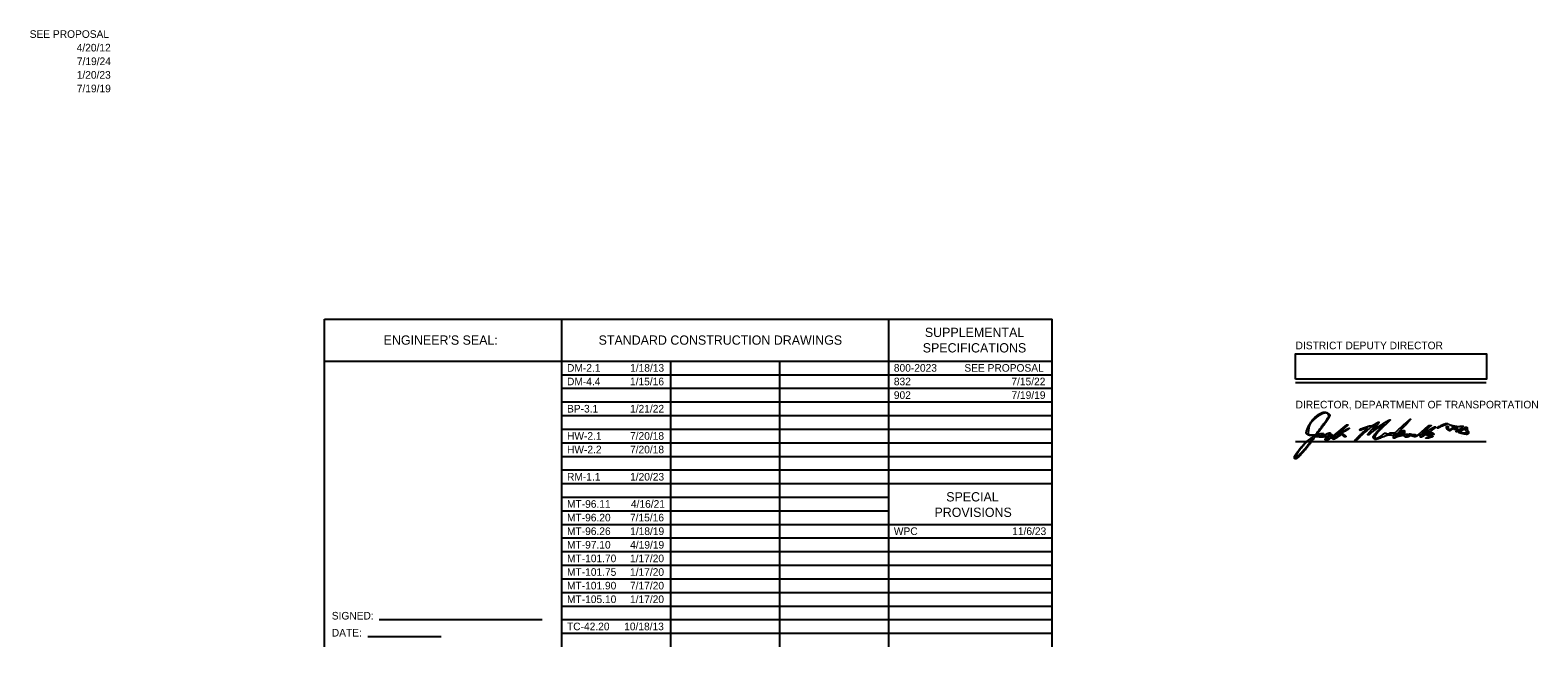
# Model space of a CAD drawing. Extents: x -84548 to 2262448, y -162180 to 525962.
# Drawn here: x 192054 to 338190, y -29401 to 30418 of the extents above; entities that cross this region are included whole.
import ezdxf

# ---------------------------------------------------------------- set-up
doc = ezdxf.new("R2010")
doc.units = 0
for name, color, linetype in [('Default', 7, 'Continuous'), ('GM_X_County', 7, 'Continuous'), ('GM_X_Section', 7, 'Continuous')]:
    doc.layers.add(name, color=color, linetype=linetype)

msp = doc.modelspace()

# ---------------------------------------------------------------- linework, layer by layer
at = {"layer": 'GM_X_County'}
for p, q in [((220590, 2389), (291110, 2389)), ((220590, -29401), (220590, 2389)), ((243590, -29401), (243590, 2389)), ((275270, -29401), (275270, 2389)), ((291110, -29401), (291110, 2389)), ((220590, -1681), (243590, -1681)), ((243590, -1681), (291110, -1681)), ((254150, -29401), (254150, -1681)), ((264710, -29401), (264710, -1681)), ((243590, -3001), (291110, -3001)), ((243590, -4321), (291110, -4321)), ((314711, -3758), (333191, -3758)), ((243590, -5641), (291110, -5641)), ((243590, -6961), (291110, -6961)), ((243590, -8281), (291110, -8281)), ((243590, -9601), (291110, -9601)), ((314711, -9492), (333191, -9492)), ((243590, -10921), (291110, -10921)), ((243590, -12241), (291110, -12241)), ((243590, -13561), (275270, -13561)), ((275270, -13561), (291110, -13561)), ((243590, -14881), (275270, -14881)), ((243590, -16201), (275270, -16201)), ((243590, -17521), (275270, -17521)), ((275270, -17521), (291110, -17521)), ((243590, -18841), (291110, -18841)), ((243590, -20161), (291110, -20161)), ((243590, -21481), (291110, -21481)), ((243590, -22801), (291110, -22801)), ((243590, -24121), (291110, -24121)), ((243590, -25441), (291110, -25441)), ((225889, -26751), (241697, -26751)), ((243590, -26761), (291110, -26761)), ((224793, -28401), (231893, -28401)), ((243590, -28081), (291110, -28081))]:
    msp.add_line(p, q, dxfattribs=at)
msp.add_lwpolyline([(314711, -3441), (314711, -987), (333213, -987), (333213, -3441)], close=True, dxfattribs=at)
at = {"layer": 'GM_X_Section'}
for p, q in [((317152, -8409), (317152, -8409)), ((328448, -8414), (328448, -8414)), ((318845, -9104), (318845, -9104)), ((319081, -8884), (319081, -8884)), ((321044, -9037), (321044, -9037)), ((325148, -8873), (325148, -8873)), ((330837, -8975), (330837, -8975))]:
    msp.add_line(p, q, dxfattribs=at)
for points in [[(324874, -8713), (324719, -8848), (324933, -8745)], [(329840, -8200), (330033, -8087), (329818, -7966)], [(331154, -8641), (331451, -8641), (331299, -8524)], [(316373, -9027), (316535, -8915), (316335, -8911)], [(317655, -9132), (317767, -8961), (317547, -9014)]]:
    msp.add_lwpolyline(points, dxfattribs=at)
for points in [[(316584, -7292), (316232, -7594), (316027, -7932), (315968, -8308)], [(316036, -7877), (316492, -7083), (317591, -6471), (317937, -6818)], [(317890, -6866), (317753, -6644), (317087, -6861), (316584, -7292)], [(317152, -8145), (317793, -7282), (317964, -6986), (317890, -6866)], [(317940, -7146), (317882, -7268), (317609, -7666), (317333, -8033)], [(317937, -6818), (318037, -6917), (318037, -6943), (317940, -7146)], [(316335, -8911), (315818, -8902), (315694, -8474), (316036, -7877)], [(315968, -8308), (315908, -8696), (316021, -8842), (316381, -8842)], [(316381, -8842), (316627, -8842), (316651, -8820), (317152, -8145)], [(317333, -8033), (317057, -8399), (316832, -8719), (316832, -8744)], [(316832, -8744), (316832, -8770), (316913, -8771), (317013, -8748)], [(316887, -8912), (317044, -8975), (317341, -8846), (317249, -8754)], [(317013, -8748), (317148, -8717), (317169, -8723), (317096, -8773)], [(317249, -8754), (317225, -8730), (317258, -8710), (317323, -8710)], [(317323, -8710), (317400, -8710), (317427, -8744), (317402, -8809)], [(317592, -8819), (317745, -8714), (318086, -8622), (318086, -8685)], [(317772, -9238), (317894, -9238), (318560, -8769), (319152, -8265)], [(318086, -8685), (318086, -8709), (318034, -8766), (317971, -8812)], [(319241, -8340), (318748, -8726), (318635, -8840), (318867, -8716)], [(318867, -8716), (318934, -8680), (319060, -8669), (319147, -8691)], [(319100, -8644), (319074, -8644), (319066, -8633), (319081, -8620)], [(319081, -8620), (319189, -8526), (319886, -8178), (319913, -8205)], [(319913, -8205), (319946, -8238), (319193, -8644), (319100, -8644)], [(319147, -8691), (319338, -8739), (319646, -9040), (319505, -9040)], [(319152, -8265), (319419, -8039), (319659, -7854), (319686, -7853)], [(319686, -7853), (319817, -7850), (319694, -7985), (319241, -8340)], [(320925, -8330), (320926, -8275), (321915, -7941), (321998, -7968)], [(322493, -7815), (322442, -7765), (321335, -8646), (320924, -9065)], [(321353, -8248), (321022, -8390), (320923, -8409), (320925, -8330)], [(321044, -8773), (321419, -8412), (321711, -8116), (321693, -8116)], [(321693, -8116), (321675, -8116), (321522, -8175), (321353, -8248)], [(321735, -8842), (321680, -8842), (321833, -8624), (322082, -8345)], [(321910, -8747), (321867, -8799), (321788, -8842), (321735, -8842)], [(323234, -7818), (322975, -7965), (321980, -8663), (321910, -8747)], [(321998, -7968), (322028, -7978), (322184, -7909), (322345, -7814)], [(322082, -8345), (322327, -8072), (322512, -7834), (322493, -7815)], [(322324, -9215), (322191, -9082), (322344, -8817), (322889, -8235)], [(322513, -7996), (322365, -8164), (322244, -8320), (322244, -8344)], [(322244, -8344), (322244, -8367), (322429, -8256), (322656, -8097)], [(322345, -7814), (322761, -7570), (322825, -7640), (322513, -7996)], [(323373, -7890), (322847, -8385), (322376, -8956), (322376, -9098)], [(322471, -9172), (322586, -9172), (323015, -8933), (323207, -8763)], [(322656, -8097), (323081, -7798), (323775, -7390), (323858, -7390)], [(322889, -8235), (323133, -7975), (323288, -7787), (323234, -7818)], [(323207, -8763), (323314, -8668), (323382, -8654), (323508, -8701)], [(323858, -7390), (323883, -7390), (323665, -7615), (323373, -7890)], [(323508, -8701), (323614, -8742), (323713, -8738), (323798, -8690)], [(323798, -8690), (323869, -8651), (324018, -8626), (324131, -8635)], [(324131, -8635), (324307, -8650), (324431, -8563), (325055, -7989)], [(324422, -8758), (324422, -8720), (324368, -8738), (324302, -8797)], [(324323, -8908), (324377, -8863), (324422, -8795), (324422, -8758)], [(325219, -8031), (324535, -8757), (324366, -9006), (324800, -8649)], [(324800, -8649), (325055, -8438), (325280, -8383), (325280, -8532)], [(325148, -8609), (325148, -8538), (325020, -8586), (324874, -8713)], [(324933, -8745), (325051, -8687), (325148, -8626), (325148, -8609)], [(325055, -7989), (325451, -7624), (325799, -7325), (325830, -7325)], [(325200, -8697), (325139, -8758), (325170, -8776), (325341, -8776)], [(325280, -8532), (325280, -8579), (325244, -8653), (325200, -8697)], [(325830, -7325), (325860, -7324), (325585, -7642), (325219, -8031)], [(325584, -8858), (325697, -8779), (325806, -8731), (325827, -8752)], [(325827, -8752), (325848, -8772), (325971, -8789), (326100, -8789)], [(326336, -8850), (326336, -8970), (326839, -8646), (327210, -8286)], [(327590, -8168), (327199, -8490), (326930, -8773), (326930, -8861)], [(326930, -8861), (326930, -8901), (327011, -8858), (327111, -8767)], [(327111, -8767), (327394, -8510), (328170, -8034), (328259, -8064)], [(327210, -8286), (327449, -8055), (327645, -7919), (327738, -7921)], [(327606, -8607), (327345, -8688), (327448, -8760), (327721, -8687)], [(327738, -7921), (327867, -7923), (327846, -7957), (327590, -8168)], [(327788, -8519), (327769, -8542), (327688, -8581), (327606, -8607)], [(327721, -8687), (327924, -8633), (328004, -8636), (328068, -8701)], [(327969, -8740), (327775, -8693), (327705, -8814), (327887, -8884)], [(328080, -8285), (327937, -8391), (327806, -8497), (327788, -8519)], [(328068, -8701), (328135, -8769), (328116, -8777), (327969, -8740)], [(328259, -8064), (328304, -8079), (328223, -8178), (328080, -8285)], [(328448, -8150), (328448, -8084), (329255, -7713), (329354, -7733)], [(328825, -8040), (328495, -8189), (328448, -8202), (328448, -8150)], [(329354, -7733), (329464, -7754), (329468, -7752), (328825, -8040)], [(329509, -8383), (329369, -8308), (329311, -7984), (329438, -7984)], [(329438, -7984), (329474, -7984), (329504, -8058), (329504, -8149)], [(329504, -8149), (329504, -8343), (329579, -8355), (329840, -8200)], [(329904, -8286), (329692, -8426), (329622, -8443), (329509, -8383)], [(329818, -7966), (329591, -7838), (329586, -7838), (330131, -7978)], [(330155, -8226), (330284, -8070), (330201, -8090), (329904, -8286)], [(330258, -8288), (330083, -8331), (330073, -8325), (330155, -8226)], [(330131, -7978), (330240, -8005), (330477, -8020), (330659, -8010)], [(330364, -8344), (330441, -8252), (330429, -8245), (330258, -8288)], [(330515, -8391), (330347, -8549), (330225, -8512), (330364, -8344)], [(330648, -8458), (330809, -8280), (330695, -8222), (330515, -8391)], [(330837, -8711), (330548, -8642), (330518, -8602), (330648, -8458)], [(330659, -8010), (330948, -7994), (330974, -8002), (330869, -8080)], [(330873, -8405), (330648, -8569), (330734, -8642), (331154, -8641)], [(330869, -8080), (330717, -8194), (330838, -8280), (331016, -8185)], [(331461, -8673), (331419, -8784), (331201, -8797), (330837, -8711)], [(331195, -8284), (331247, -8148), (331204, -8164), (330873, -8405)], [(331016, -8185), (331228, -8071), (331352, -8102), (331352, -8268)], [(331299, -8524), (331191, -8441), (331161, -8372), (331195, -8284)], [(331352, -8268), (331352, -8351), (331385, -8453), (331426, -8494)], [(331426, -8494), (331468, -8535), (331483, -8616), (331461, -8673)], [(316158, -9601), (315354, -10668), (314588, -11347), (314588, -10993)], [(316335, -9181), (316225, -9071), (315071, -10262), (314826, -10739)], [(315048, -10306), (315458, -9775), (315880, -9367), (316373, -9027)], [(315196, -10640), (315553, -10276), (316376, -9222), (316335, -9181)], [(316801, -9026), (316625, -9009), (316563, -9064), (316158, -9601)], [(316865, -8845), (316746, -8850), (316749, -8857), (316887, -8912)], [(317547, -9014), (317334, -9066), (317216, -9068), (316801, -9026)], [(317096, -8773), (317041, -8810), (316937, -8842), (316865, -8845)], [(317402, -8809), (317355, -8932), (317422, -8935), (317592, -8819)], [(317649, -9343), (317553, -9306), (317554, -9287), (317655, -9132)], [(318000, -9239), (317865, -9318), (317707, -9365), (317649, -9343)], [(318007, -8970), (317738, -9119), (317634, -9238), (317772, -9238)], [(317971, -8812), (317872, -8885), (317882, -8892), (318054, -8866)], [(318271, -9166), (318256, -9121), (318154, -9148), (318000, -9239)], [(318054, -8866), (318248, -8836), (318247, -8838), (318007, -8970)], [(318875, -9009), (318511, -9243), (318313, -9294), (318271, -9166)], [(318564, -8927), (318330, -9141), (318390, -9188), (318696, -9031)], [(318845, -8840), (318754, -8806), (318667, -8833), (318564, -8927)], [(318696, -9031), (318941, -8907), (318960, -8882), (318845, -8840)], [(319322, -8910), (319233, -8783), (319222, -8785), (318875, -9009)], [(319505, -9040), (319455, -9040), (319372, -8981), (319322, -8910)], [(320462, -9432), (320407, -9431), (320669, -9135), (321044, -8773)], [(320924, -9065), (320724, -9268), (320516, -9433), (320462, -9432)], [(323378, -8964), (322607, -9269), (322422, -9313), (322324, -9215)], [(322376, -9098), (322376, -9139), (322418, -9172), (322471, -9172)], [(323935, -8873), (323781, -8854), (323571, -8888), (323378, -8964)], [(324302, -8797), (324220, -8872), (324108, -8896), (323935, -8873)], [(324286, -9172), (324189, -9172), (324213, -8999), (324323, -8908)], [(324382, -9117), (324363, -9147), (324320, -9172), (324286, -9172)], [(324784, -8974), (324581, -9023), (324400, -9087), (324382, -9117)], [(325229, -8963), (325170, -8904), (325064, -8907), (324784, -8974)], [(325738, -8976), (325575, -9063), (325323, -9056), (325229, -8963)], [(325341, -8776), (325539, -8776), (325551, -8787), (325469, -8889)], [(325469, -8889), (325406, -8968), (325440, -8959), (325584, -8858)], [(326078, -8976), (325936, -8935), (325814, -8935), (325738, -8976)], [(326548, -8916), (326351, -9014), (326253, -9026), (326078, -8976)], [(326100, -8789), (326230, -8789), (326336, -8816), (326336, -8850)], [(326798, -8916), (326798, -8795), (326792, -8795), (326548, -8916)], [(327125, -8932), (326887, -9073), (326798, -9068), (326798, -8916)], [(327564, -8890), (327359, -8838), (327270, -8846), (327125, -8932)], [(327754, -9106), (327508, -9187), (327258, -9157), (327491, -9074)], [(327491, -9074), (327563, -9048), (327667, -9011), (327722, -8991)], [(327722, -8991), (327782, -8969), (327720, -8930), (327564, -8890)], [(327887, -8884), (328048, -8946), (328001, -9025), (327754, -9106)], [(314588, -10993), (314588, -10943), (314795, -10633), (315048, -10306)], [(314826, -10739), (314661, -11061), (314828, -11017), (315196, -10640)]]:
    msp.add_open_spline(points, degree=2, dxfattribs=at)

# ---------------------------------------------------------------- texts
at = {"layer": 'Default'}
for s, p in [('DISTRICT DEPUTY DIRECTOR', (314711, -537)), ('DIRECTOR, DEPARTMENT OF TRANSPORTATION', (314711, -6271))]:
    msp.add_text(s, height=739.2, dxfattribs=at).set_placement(p)
at = {"layer": 'GM_X_County'}
for s, height, p in [('SEE PROPOSAL', 739.2, (192010, 29668)), ('4/20/12', 739.2, (196564, 28348)), ('7/19/24', 739.2, (196582, 27028)), ('1/20/23', 739.2, (196569, 25708)), ('7/19/19', 739.2, (196575, 24388)), ('SUPPLEMENTAL', 900, (278776, 654)), ("ENGINEER'S SEAL:", 900, (226317, -96)), ('STANDARD CONSTRUCTION DRAWINGS', 900, (247153, -96)), ('SPECIFICATIONS', 900, (278570, -846)), ('DM-2.1', 739.2, (244090, -2711)), ('1/18/13', 739.2, (250205, -2711)), ('800-2023', 739.2, (275770, -2711)), ('SEE PROPOSAL', 739.2, (282606, -2711)), ('DM-4.4', 739.2, (244090, -4031)), ('1/15/16', 739.2, (250194, -4031)), ('832', 739.2, (275770, -4031)), ('7/15/22', 739.2, (287160, -4031)), ('902', 739.2, (275770, -5351)), ('7/19/19', 739.2, (287171, -5351)), ('BP-3.1', 739.2, (244090, -6671)), ('1/21/22', 739.2, (250200, -6671)), ('HW-2.1', 739.2, (244090, -9311)), ('7/20/18', 739.2, (250197, -9311)), ('HW-2.2', 739.2, (244090, -10631)), ('7/20/18', 739.2, (250197, -10631)), ('RM-1.1', 739.2, (244090, -13271)), ('1/20/23', 739.2, (250205, -13271)), ('SPECIAL', 900, (280847, -15297)), ('MT-96.11', 739.2, (244090, -15911)), ('4/16/21', 739.2, (250285, -15911)), ('PROVISIONS', 900, (279709, -16797)), ('MT-96.20', 739.2, (244090, -17231)), ('7/15/16', 739.2, (250194, -17231)), ('MT-96.26', 739.2, (244090, -18551)), ('1/18/19', 739.2, (250211, -18551)), ('WPC', 739.2, (275770, -18551)), ('11/6/23', 739.2, (287241, -18551)), ('MT-97.10', 739.2, (244090, -19871)), ('MT-101.70', 739.2, (244090, -21191)), ('4/19/19', 739.2, (250211, -19871)), ('1/17/20', 739.2, (250196, -21191)), ('MT-101.75', 739.2, (244090, -22511)), ('1/17/20', 739.2, (250196, -22511)), ('MT-101.90', 739.2, (244090, -23831)), ('7/17/20', 739.2, (250196, -23831)), ('MT-105.10', 739.2, (244090, -25151)), ('1/17/20', 739.2, (250196, -25151)), ('SIGNED:', 739.2, (221290, -26751)), ('DATE:', 739.2, (221290, -28401)), ('TC-42.20', 739.2, (244090, -27791)), ('10/18/13', 739.2, (249631, -27791))]:
    msp.add_text(s, height=height, dxfattribs=at).set_placement(p)

doc.saveas('drawing.dxf')
